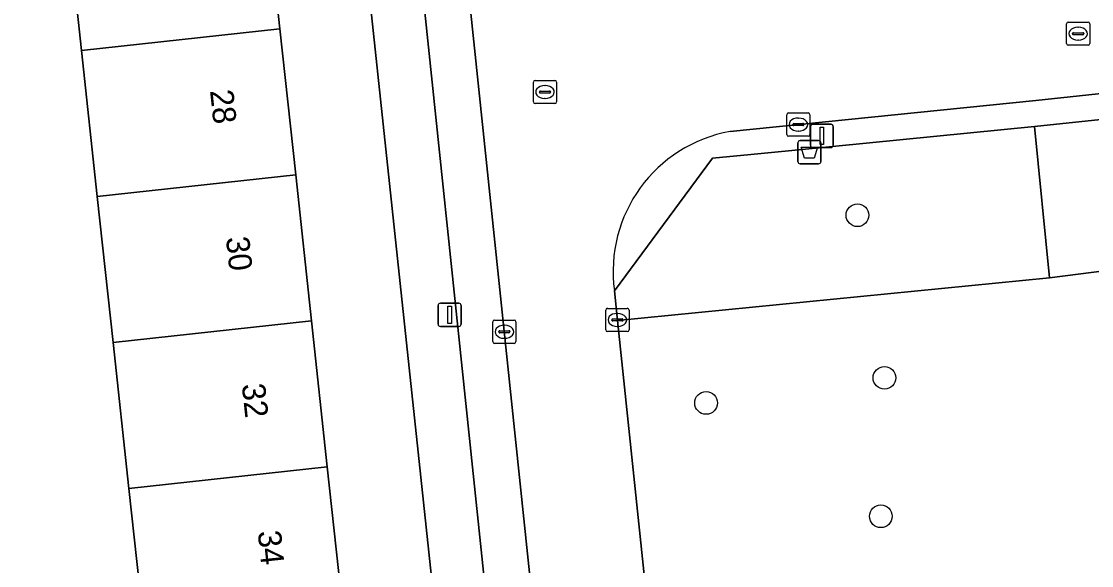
# Model space of a CAD drawing. Extents: x 160554 to 161248, y 385329 to 386506.
# Drawn here: x 160749.76 to 160795.83, y 386030.91 to 386054.36 of the extents above; entities that cross this region are included whole.
import ezdxf

# ---------------------------------------------------------------- set-up
doc = ezdxf.new("R2010")
doc.units = 0
for name, color, linetype in [('IMGEO_Afvalbak', 7, 'Continuous'), ('IMGEO_Boom', 7, 'Continuous'), ('IMGEO_Erf', 7, 'Continuous'), ('IMGEO_Groenvoorziening', 7, 'Continuous'), ('IMGEO_Kolk', 7, 'Continuous'), ('IMGEO_Lichtmast', 7, 'Continuous'), ('IMGEO_Pand', 7, 'Continuous'), ('IMGEO_Pand_nummerreeks', 7, 'Continuous'), ('IMGEO_Parkeervlak_open', 7, 'Continuous'), ('IMGEO_Rijbaan_lokaal_open', 7, 'Continuous'), ('IMGEO_Rioolput', 7, 'Continuous'), ('IMGEO_Voetpad_open', 7, 'Continuous')]:
    doc.layers.add(name, color=color, linetype=linetype)

msp = doc.modelspace()

# ---------------------------------------------------------------- linework, layer by layer
at = {"layer": 'IMGEO_Afvalbak'}
for p, q in [((160783.187, 386048.32), (160783.187, 386049.12)), ((160783.187, 386049.12), (160783.187, 386048.32)), ((160783.287, 386049.22), (160784.077, 386049.22)), ((160784.077, 386049.22), (160783.287, 386049.22)), ((160784.177, 386049.12), (160784.177, 386048.32)), ((160784.177, 386048.32), (160784.177, 386049.12)), ((160784.077, 386048.22), (160783.287, 386048.22)), ((160783.287, 386048.22), (160784.077, 386048.22))]:
    msp.add_line(p, q, dxfattribs=at)
msp.add_lwpolyline([(160783.33, 386048.934), (160784.034, 386048.934), (160783.885, 386048.464), (160783.479, 386048.464), (160783.33, 386048.934)], dxfattribs=at)
for centre, start, end in [((160783.287, 386049.12), 90, 180), ((160783.287, 386049.12), 90, 180), ((160784.077, 386049.12), 0, 90), ((160784.077, 386049.12), 360, 90), ((160783.287, 386048.32), 180, 270), ((160783.287, 386048.32), 180, 270), ((160784.077, 386048.32), 270, 0), ((160784.077, 386048.32), 270, 0)]:
    msp.add_arc(centre, 0.1, start, end, dxfattribs=at)
at = {"layer": 'IMGEO_Boom'}
for centre in [(160785.752, 386046.006), (160786.914, 386039.001), (160779.236, 386037.917), (160786.759, 386033.034)]:
    msp.add_circle(centre, 0.489, dxfattribs=at)
at = {"layer": 'IMGEO_Erf'}
for points in [[(160755.067, 386027.946), (160754.388, 386034.237), (160753.708, 386040.527), (160753.029, 386046.818), (160752.35, 386053.108), (160751.67, 386059.398), (160750.991, 386065.689), (160747.799, 386065.345), (160747.467, 386068.42), (160750.659, 386068.765), (160750.293, 386072.152), (160758.833, 386073.075), (160759.531, 386066.611), (160760.211, 386060.32), (160760.89, 386054.03), (160761.57, 386047.74), (160762.249, 386041.449), (160762.929, 386035.159), (160763.608, 386028.868)], [(160770.665, 386000), (160762.861, 386073.091)]]:
    msp.add_lwpolyline(points, dxfattribs=at)
at = {"layer": 'IMGEO_Groenvoorziening'}
msp.add_lwpolyline([(160840.381, 386054.785), (160814.075, 386052.015), (160814.418, 386045.903), (160804.223, 386044.608), (160794.027, 386043.313), (160775.425, 386041.464), (160779.77, 386000), (160780.285, 385995.082)], dxfattribs=at)
for points in [[(160803.725, 386050.924), (160793.379, 386049.834), (160794.027, 386043.313), (160804.223, 386044.608)], [(160793.379, 386049.834), (160783.369, 386048.84), (160781.169, 386048.621), (160779.517, 386048.457), (160775.29, 386042.75), (160775.425, 386041.464), (160794.027, 386043.313)]]:
    msp.add_lwpolyline(points, close=True, dxfattribs=at)
at = {"layer": 'IMGEO_Kolk'}
for p, q in [((160782.708, 386049.484), (160782.708, 386050.336)), ((160782.783, 386050.41), (160783.635, 386050.41)), ((160783.709, 386050.336), (160783.709, 386049.484)), ((160782.967, 386049.904), (160782.967, 386049.916)), ((160783.405, 386049.867), (160783.007, 386049.867)), ((160783.01, 386049.953), (160783.408, 386049.953)), ((160783.196, 386050.19), (160783.221, 386050.19)), ((160783.451, 386049.916), (160783.451, 386049.904)), ((160783.635, 386049.41), (160782.783, 386049.41)), ((160783.219, 386049.63), (160783.194, 386049.63)), ((160774.993, 386041.994), (160775.845, 386041.994)), ((160774.918, 386041.068), (160774.918, 386041.92)), ((160775.177, 386041.488), (160775.177, 386041.5)), ((160775.22, 386041.537), (160775.618, 386041.537)), ((160775.406, 386041.774), (160775.431, 386041.774)), ((160775.661, 386041.5), (160775.661, 386041.488)), ((160775.919, 386041.92), (160775.919, 386041.068)), ((160770.051, 386040.559), (160770.051, 386041.411)), ((160770.126, 386041.485), (160770.978, 386041.485)), ((160770.539, 386041.265), (160770.564, 386041.265)), ((160771.052, 386041.411), (160771.052, 386040.559)), ((160775.615, 386041.451), (160775.217, 386041.451)), ((160775.429, 386041.214), (160775.404, 386041.214)), ((160770.31, 386040.979), (160770.31, 386040.991)), ((160770.748, 386040.942), (160770.35, 386040.942)), ((160770.353, 386041.028), (160770.751, 386041.028)), ((160770.562, 386040.705), (160770.537, 386040.705)), ((160770.794, 386040.991), (160770.794, 386040.979)), ((160775.845, 386040.994), (160774.993, 386040.994)), ((160770.978, 386040.485), (160770.126, 386040.485))]:
    msp.add_line(p, q, dxfattribs=at)
for points in [[(160782.708, 386049.484), (160782.708, 386050.336)], [(160782.783, 386050.41), (160783.635, 386050.41)], [(160783.709, 386050.336), (160783.709, 386049.484)], [(160783.635, 386049.41), (160782.783, 386049.41)], [(160774.993, 386041.994), (160775.845, 386041.994)], [(160774.918, 386041.068), (160774.918, 386041.92)], [(160775.919, 386041.92), (160775.919, 386041.068)], [(160770.051, 386040.559), (160770.051, 386041.411)], [(160770.126, 386041.485), (160770.978, 386041.485)], [(160771.052, 386041.411), (160771.052, 386040.559)], [(160775.845, 386040.994), (160774.993, 386040.994)], [(160770.978, 386040.485), (160770.126, 386040.485)]]:
    msp.add_lwpolyline(points, dxfattribs=at)
for centre, radius, start, end in [((160782.785, 386050.334), 0.0765, 91.552, 178.448), ((160782.785, 386050.334), 0.0765, 91.552, 178.448), ((160783.633, 386050.334), 0.0765, 1.552, 88.448), ((160783.633, 386050.334), 0.0765, 1.552, 88.448), ((160783.007, 386049.913), 0.0403, 85.8775, 175.7526), ((160783.004, 386049.903), 0.0366, 178.938, 274.7102), ((160783.408, 386049.91), 0.043, 264.8664, 352.4533), ((160783.412, 386049.915), 0.0386, 1.7309, 96.639), ((160782.785, 386049.486), 0.0765, 181.552, 268.448), ((160782.785, 386049.486), 0.0765, 181.552, 268.448), ((160783.633, 386049.486), 0.0765, 271.552, 358.448), ((160783.633, 386049.486), 0.0765, 271.552, 358.448), ((160774.995, 386041.918), 0.0765, 91.552, 178.448), ((160774.995, 386041.918), 0.0765, 91.552, 178.448), ((160775.843, 386041.918), 0.0765, 1.552, 88.448), ((160775.843, 386041.918), 0.0765, 1.552, 88.448), ((160775.217, 386041.497), 0.0403, 85.8775, 175.7526), ((160775.622, 386041.499), 0.0386, 1.7309, 96.639), ((160770.128, 386041.409), 0.0765, 91.552, 178.448), ((160770.128, 386041.409), 0.0765, 91.552, 178.448), ((160770.976, 386041.409), 0.0765, 1.552, 88.448), ((160770.976, 386041.409), 0.0765, 1.552, 88.448), ((160774.995, 386041.07), 0.0765, 181.552, 268.448), ((160774.995, 386041.07), 0.0765, 181.552, 268.448), ((160775.214, 386041.487), 0.0366, 178.938, 274.7102), ((160775.618, 386041.494), 0.043, 264.8664, 352.4533), ((160775.843, 386041.07), 0.0765, 271.552, 358.448), ((160775.843, 386041.07), 0.0765, 271.552, 358.448), ((160770.35, 386040.988), 0.0403, 85.8775, 175.7526), ((160770.347, 386040.978), 0.0366, 178.938, 274.7102), ((160770.751, 386040.985), 0.043, 264.8664, 352.4533), ((160770.755, 386040.99), 0.0386, 1.7309, 96.639), ((160770.128, 386040.561), 0.0765, 181.552, 268.448), ((160770.128, 386040.561), 0.0765, 181.552, 268.448), ((160770.976, 386040.561), 0.0765, 271.552, 358.448), ((160770.976, 386040.561), 0.0765, 271.552, 358.448)]:
    msp.add_arc(centre, radius, start, end, dxfattribs=at)
for centre, major_axis, ratio, start_param, end_param in [((160783.195, 386049.91), (-0.387, 0.002), 0.722429, 4.712389, 7.853982), ((160783.22, 386049.91), (-0.39, 0.002), 0.717154, 1.570796, 4.712389), ((160775.405, 386041.494), (-0.387, 0.002), 0.722429, 4.712389, 7.853982), ((160775.43, 386041.494), (-0.39, 0.002), 0.717154, 1.570796, 4.712389), ((160770.538, 386040.985), (-0.387, 0.002), 0.722429, 4.712389, 7.853982), ((160770.563, 386040.985), (-0.39, 0.002), 0.717154, 1.570796, 4.712389)]:
    msp.add_ellipse(centre, major_axis=major_axis, ratio=ratio, start_param=start_param, end_param=end_param, dxfattribs=at)
at = {"layer": 'IMGEO_Lichtmast'}
for p, q in [((160783.724, 386049.022), (160783.724, 386049.822)), ((160783.724, 386049.822), (160783.724, 386049.022)), ((160783.824, 386049.922), (160784.614, 386049.922)), ((160784.614, 386049.922), (160783.824, 386049.922)), ((160784.714, 386049.822), (160784.714, 386049.022)), ((160784.714, 386049.022), (160784.714, 386049.822)), ((160784.614, 386048.922), (160783.824, 386048.922)), ((160783.824, 386048.922), (160784.614, 386048.922)), ((160767.699, 386041.314), (160767.699, 386042.114)), ((160767.699, 386042.114), (160767.699, 386041.314)), ((160767.799, 386042.214), (160768.589, 386042.214)), ((160768.589, 386042.214), (160767.799, 386042.214)), ((160768.689, 386042.114), (160768.689, 386041.314)), ((160768.689, 386041.314), (160768.689, 386042.114)), ((160768.589, 386041.214), (160767.799, 386041.214)), ((160767.799, 386041.214), (160768.589, 386041.214))]:
    msp.add_line(p, q, dxfattribs=at)
for points in [[(160784.144, 386049.797), (160784.294, 386049.797), (160784.294, 386049.047), (160784.144, 386049.047), (160784.144, 386049.797)], [(160768.119, 386042.089), (160768.269, 386042.089), (160768.269, 386041.339), (160768.119, 386041.339), (160768.119, 386042.089)]]:
    msp.add_lwpolyline(points, dxfattribs=at)
for centre, start, end in [((160783.824, 386049.822), 90, 180), ((160783.824, 386049.822), 90, 180), ((160784.614, 386049.822), 0, 90), ((160784.614, 386049.822), 360, 90), ((160783.824, 386049.022), 180, 270), ((160783.824, 386049.022), 180, 270), ((160784.614, 386049.022), 270, 0), ((160784.614, 386049.022), 270, 0), ((160767.799, 386042.114), 90, 180), ((160767.799, 386042.114), 90, 180), ((160768.589, 386042.114), 0, 90), ((160768.589, 386042.114), 360, 90), ((160767.799, 386041.314), 180, 270), ((160767.799, 386041.314), 180, 270), ((160768.589, 386041.314), 270, 0), ((160768.589, 386041.314), 270, 0)]:
    msp.add_arc(centre, 0.1, start, end, dxfattribs=at)
at = {"layer": 'IMGEO_Pand'}
for points in [[(160751.67, 386059.398), (160752.35, 386053.108), (160760.89, 386054.03), (160760.211, 386060.32)], [(160761.57, 386047.74), (160760.89, 386054.03), (160752.35, 386053.108), (160753.029, 386046.818)], [(160753.029, 386046.818), (160753.708, 386040.527), (160762.249, 386041.449), (160761.57, 386047.74)], [(160762.929, 386035.159), (160762.249, 386041.449), (160753.708, 386040.527), (160754.388, 386034.237)], [(160754.388, 386034.237), (160755.067, 386027.946), (160763.608, 386028.868), (160762.929, 386035.159)]]:
    msp.add_lwpolyline(points, close=True, dxfattribs=at)
at = {"layer": 'IMGEO_Parkeervlak_open'}
for points in [[(160774.765, 385986.114), (160775.99, 385985.247), (160776.471, 385984.724), (160774.881, 386000), (160772.645, 386021.005), (160767.112, 386073.774)], [(160765.519, 386070.113), (160770.498, 386022.549), (160770.681, 386020.798), (160771.058, 386017.254), (160772.895, 386000), (160774.286, 385986.931)]]:
    msp.add_lwpolyline(points, dxfattribs=at)
at = {"layer": 'IMGEO_Rijbaan_lokaal_open'}
for points in [[(160790.865, 386085.285), (160790.452, 386085.264), (160789.868, 386085.202), (160766.741, 386082.763), (160766.152, 386082.701), (160766.611, 386078.562), (160766.791, 386076.943), (160766.961, 386075.32), (160767.112, 386073.774), (160772.645, 386021.005), (160774.881, 386000), (160776.471, 385984.724), (160780.562, 385985.145), (160788.954, 385985.976), (160801.932, 385987.281), (160825.874, 385989.726), (160847.456, 385991.944), (160851.678, 385992.378)], [(160780.273, 386049.615), (160793.437, 386050.941), (160818.277, 386053.611), (160842.658, 386056.111)], [(160780.285, 385995.082), (160779.77, 386000), (160775.425, 386041.464), (160775.29, 386042.75)]]:
    msp.add_lwpolyline(points, dxfattribs=at)
msp.add_arc((160781.362, 386043.584), 6.129, 100.2335, 187.818, dxfattribs=at)
at = {"layer": 'IMGEO_Rioolput'}
for p, q in [((160794.755, 386053.401), (160794.755, 386054.253)), ((160794.83, 386054.327), (160795.682, 386054.327)), ((160795.243, 386054.107), (160795.268, 386054.107)), ((160795.756, 386054.253), (160795.756, 386053.401)), ((160795.014, 386053.821), (160795.014, 386053.833)), ((160795.452, 386053.784), (160795.054, 386053.784)), ((160795.057, 386053.87), (160795.455, 386053.87)), ((160795.266, 386053.547), (160795.241, 386053.547)), ((160795.498, 386053.833), (160795.498, 386053.821)), ((160795.682, 386053.327), (160794.83, 386053.327)), ((160771.8, 386050.888), (160771.8, 386051.74)), ((160771.875, 386051.814), (160772.727, 386051.814)), ((160772.801, 386051.74), (160772.801, 386050.888)), ((160772.059, 386051.308), (160772.059, 386051.32)), ((160772.497, 386051.271), (160772.099, 386051.271)), ((160772.102, 386051.357), (160772.5, 386051.357)), ((160772.288, 386051.594), (160772.313, 386051.594)), ((160772.543, 386051.32), (160772.543, 386051.308)), ((160772.727, 386050.814), (160771.875, 386050.814)), ((160772.311, 386051.034), (160772.286, 386051.034))]:
    msp.add_line(p, q, dxfattribs=at)
for points in [[(160794.755, 386053.401), (160794.755, 386054.253)], [(160794.83, 386054.327), (160795.682, 386054.327)], [(160795.756, 386054.253), (160795.756, 386053.401)], [(160795.682, 386053.327), (160794.83, 386053.327)], [(160771.8, 386050.888), (160771.8, 386051.74)], [(160771.875, 386051.814), (160772.727, 386051.814)], [(160772.801, 386051.74), (160772.801, 386050.888)], [(160772.727, 386050.814), (160771.875, 386050.814)]]:
    msp.add_lwpolyline(points, dxfattribs=at)
for centre, radius, start, end in [((160794.832, 386054.251), 0.0765, 91.552, 178.448), ((160794.832, 386054.251), 0.0765, 91.552, 178.448), ((160795.68, 386054.251), 0.0765, 1.552, 88.448), ((160795.68, 386054.251), 0.0765, 1.552, 88.448), ((160795.054, 386053.83), 0.0403, 85.8775, 175.7526), ((160795.051, 386053.82), 0.0366, 178.938, 274.7102), ((160795.455, 386053.827), 0.043, 264.8664, 352.4533), ((160795.459, 386053.832), 0.0386, 1.7309, 96.639), ((160794.832, 386053.403), 0.0765, 181.552, 268.448), ((160794.832, 386053.403), 0.0765, 181.552, 268.448), ((160795.68, 386053.403), 0.0765, 271.552, 358.448), ((160795.68, 386053.403), 0.0765, 271.552, 358.448), ((160771.877, 386051.738), 0.0765, 91.552, 178.448), ((160771.877, 386051.738), 0.0765, 91.552, 178.448), ((160772.725, 386051.738), 0.0765, 1.552, 88.448), ((160772.725, 386051.738), 0.0765, 1.552, 88.448), ((160772.099, 386051.317), 0.0403, 85.8775, 175.7526), ((160772.096, 386051.307), 0.0366, 178.938, 274.7102), ((160772.5, 386051.314), 0.043, 264.8664, 352.4533), ((160772.504, 386051.319), 0.0386, 1.7309, 96.639), ((160771.877, 386050.89), 0.0765, 181.552, 268.448), ((160771.877, 386050.89), 0.0765, 181.552, 268.448), ((160772.725, 386050.89), 0.0765, 271.552, 358.448), ((160772.725, 386050.89), 0.0765, 271.552, 358.448)]:
    msp.add_arc(centre, radius, start, end, dxfattribs=at)
for centre, major_axis, ratio, start_param, end_param in [((160795.242, 386053.827), (-0.387, 0.002), 0.722429, 4.712389, 7.853982), ((160795.267, 386053.827), (-0.39, 0.002), 0.717154, 1.570796, 4.712389), ((160772.287, 386051.314), (-0.387, 0.002), 0.722429, 4.712389, 7.853982), ((160772.312, 386051.314), (-0.39, 0.002), 0.717154, 1.570796, 4.712389)]:
    msp.add_ellipse(centre, major_axis=major_axis, ratio=ratio, start_param=start_param, end_param=end_param, dxfattribs=at)
at = {"layer": 'IMGEO_Voetpad_open'}
for points in [[(160766.961, 386075.32), (160766.791, 386076.943), (160766.611, 386078.562), (160766.115, 386078.507), (160762.424, 386078.221), (160762.861, 386073.091), (160770.665, 386000), (160773.674, 385971.815), (160772.629, 385971.543), (160773.921, 385965.761), (160776.074, 385966.255)], [(160774.286, 385986.931), (160772.895, 386000), (160771.058, 386017.254), (160770.561, 386017.202), (160770.001, 386022.497), (160770.498, 386022.549), (160765.519, 386070.113)], [(160842.163, 386053.49), (160842.658, 386056.111), (160818.277, 386053.611), (160793.437, 386050.941), (160780.273, 386049.615)], [(160775.29, 386042.75), (160779.517, 386048.457), (160781.169, 386048.621), (160783.369, 386048.84), (160793.379, 386049.834), (160803.725, 386050.924), (160814.069, 386052.014)]]:
    msp.add_lwpolyline(points, dxfattribs=at)
msp.add_arc((160781.362, 386043.584), 6.129, 100.2335, 187.818, dxfattribs=at)

# ---------------------------------------------------------------- texts
at = {"layer": 'IMGEO_Pand_nummerreeks'}
for s, p in [('28', (160757.878, 386051.374)), ('30', (160758.562, 386045.041)), ('32', (160759.245, 386038.713)), ('34', (160759.93, 386032.377))]:
    msp.add_text(s, height=1, rotation=276.165, dxfattribs=at).set_placement(p)

doc.saveas('drawing.dxf')
